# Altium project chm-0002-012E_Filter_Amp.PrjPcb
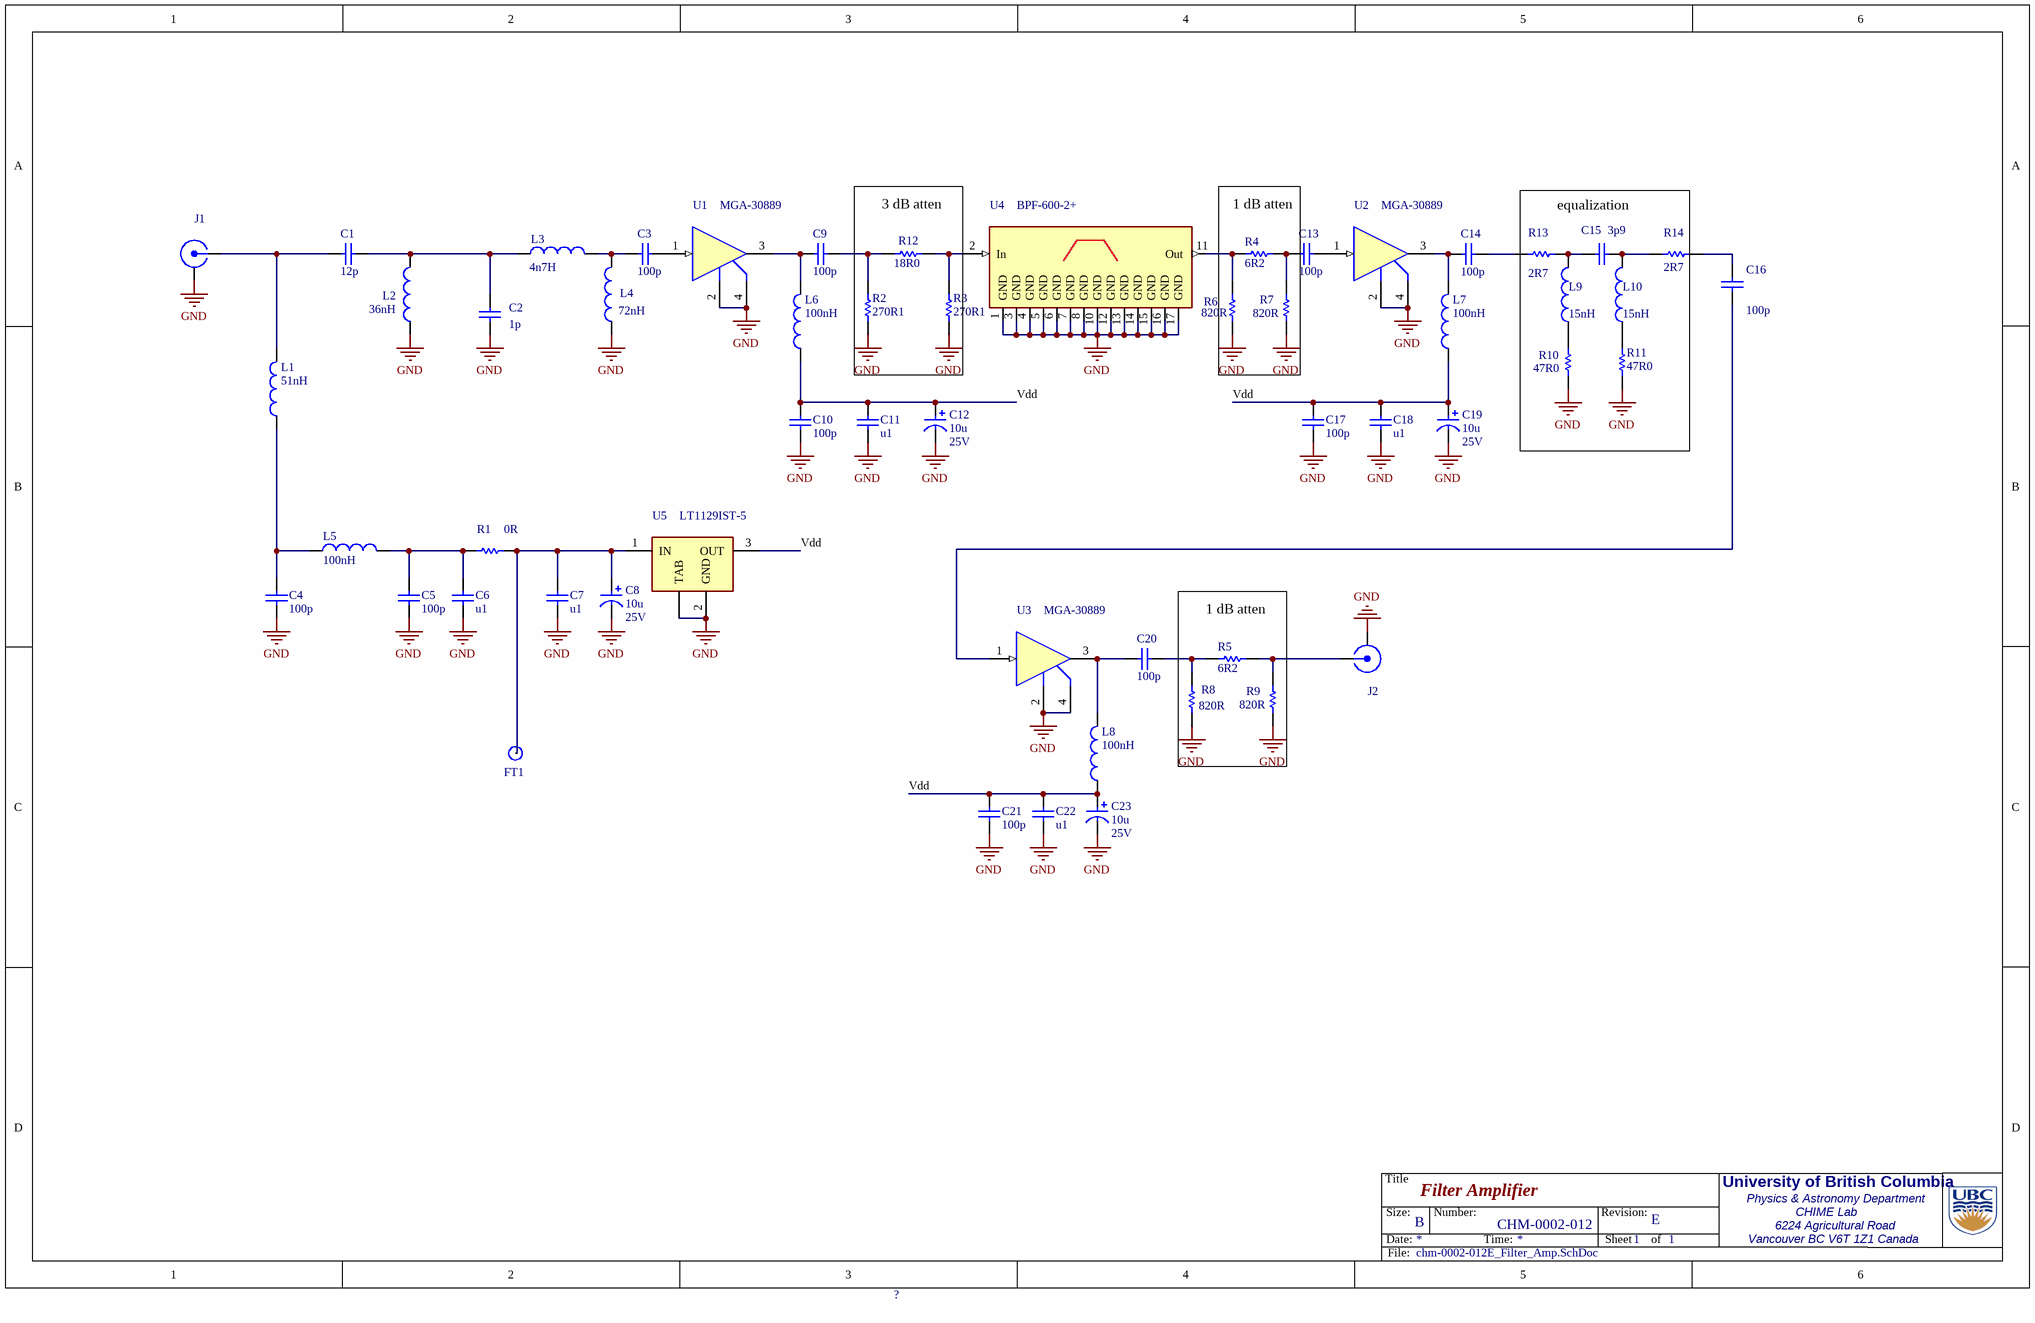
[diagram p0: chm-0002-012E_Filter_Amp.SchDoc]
ASYNumber: 00XXXX ASY; Board#: ****; BOMTitle: CHIME - Filter Amplifier; PO_Number: ****; Project: CHIME Project; Rev: CHM-0002-012 Rev E; Speedchart: LSCS
1 sheet, 56 parts. Net scope: global (net labels, ports and power ports of the same name join across sheets).
Board file: chm-0002-012E_Filter_Amp.PcbDoc

## Sheet chm-0002-012E_Filter_Amp.SchDoc: Filter Amplifier
size B; DrawnBy: V.Soutyrine; Engineer: Rick Smegal; Organization: University of British Columbia; Address1: Physics & Astronomy Department; Address2: CHIME Lab; Address3: 6224 Agricultural Road; Address4: Vancouver BC V6T 1Z1 Canada; DocumentNumber: CHM-0002-012; Revision: E; SheetNumber: 1; SheetTotal: 1

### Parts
?  UBC Logo  [UBC Logo]  (value not drawn)
C1  value 12p  [C1608-0603]  (hidden comment: C0603_12p)
C2  value 1p  [C1608-0603]  (hidden comment: C0603_1p)
C3  value 100p  [C1608-0603]  (hidden comment: C0603_100p)
C4  value 100p  [C1608-0603]  (hidden comment: C0603_100p)
C5  value 100p  [C1608-0603]  (hidden comment: C0603_100p)
C6  value u1  [C1608-0603]  (hidden comment: C0603_u1)
C7  value u1  [C1608-0603]  (hidden comment: C0603_u1)
C8  value 10u  Voltage: 25V  [CC3528]  (hidden comment: Cap Tant 10uF 25V Low ESR)
C9  value 100p  [C1608-0603]  (hidden comment: C0603_100p)
C10  value 100p  [C1608-0603]  (hidden comment: C0603_100p)
C11  value u1  [C1608-0603]  (hidden comment: C0603_u1)
C12  value 10u  Voltage: 25V  [CC3528]  (hidden comment: Cap Tant 10uF 25V Low ESR)
C13  value 100p  [C1608-0603]  (hidden comment: C0603_100p)
C14  value 100p  [C1608-0603]  (hidden comment: C0603_100p)
C15  value 3p9  [C1608-0603]  (hidden comment: C0603_3p9)
C16  value 100p  [C1608-0603]  (hidden comment: C0603_100p)
C17  value 100p  [C1608-0603]  (hidden comment: C0603_100p)
C18  value u1  [C1608-0603]  (hidden comment: C0603_u1)
C19  value 10u  Voltage: 25V  [CC3528]  (hidden comment: Cap Tant 10uF 25V Low ESR)
C20  value 100p  [C1608-0603]  (hidden comment: C0603_100p)
C21  value 100p  [C1608-0603]  (hidden comment: C0603_100p)
C22  value u1  [C1608-0603]  (hidden comment: C0603_u1)
C23  value 10u  Voltage: 25V  [CC3528]  (hidden comment: Cap Tant 10uF 25V Low ESR)
FT1  #6 Clearance Drill  [#6 Clearance Drill]  (value not drawn)
J1  SMA-Edgemount  [SMA_EdgeConnector]  (value not drawn)
J2  SMA-Edgemount  [SMA_EdgeConnector]  (value not drawn)
L1  value 51nH  [R0603]  (hidden comment: Ind0603_51nH)
L2  value 36nH  [R0603]  (hidden comment: Ind0603_36nH)
L3  value 4n7H  [R0603]  (hidden comment: Ind0603_4n7H)
L4  value 72nH  [R0603]  (hidden comment: Ind0603_72nH)
L5  value 100nH  [0805 LRC]  (hidden comment: Ind0805_100nH)
L6  value 100nH  [R0603]  (hidden comment: Ind0603_100nH)
L7  value 100nH  [R0603]  (hidden comment: Ind0603_100nH)
L8  value 100nH  [R0603]  (hidden comment: Ind0603_100nH)
L9  value 15nH  [R0603]  (hidden comment: Ind0603_15nH)
L10  value 15nH  [R0603]  (hidden comment: Ind0603_15nH)
R1  value 0R  [0805 LRC]  (hidden comment: R0805_0R)
R2  value 270R1  [R0603]  (hidden comment: R603_270R1)
R3  value 270R1  [R0603]  (hidden comment: R603_270R1)
R4  value 6R2  [R0603]  (hidden comment: R603_6R2)
R5  value 6R2  [R0603]  (hidden comment: R603_6R2)
R6  value 820R  [R0603]  (hidden comment: R603_82R1)
R7  value 820R  [R0603]  (hidden comment: R603_82R1)
R8  value 820R  [R0603]  (hidden comment: R603_82R1)
R9  value 820R  [R0603]  (hidden comment: R603_82R1)
R10  value 47R0  [R0603]  (hidden comment: R603_47R0)
R11  value 47R0  [R0603]  (hidden comment: R603_47R0)
R12  value 18R0  [R0603]  (hidden comment: R603_18R0)
R13  value 2R7  [R0603]  (hidden comment: R603_2R7)
R14  value 2R7  [R0603]  (hidden comment: R603_2R7)
U1  MGA-30889  [SOT-89]
U2  MGA-30889  [SOT-89]
U3  MGA-30889  [SOT-89]
U4  BPF-600-2+  [MiniCcts_HP1156]
U5  LT1129IST-5  [SOT-223]

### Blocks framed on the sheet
3 dB atten: R2 R3 R12
1 dB atten: R4 R6 R7
equalization: C15 L9 L10 R10 R11 R13 R14
1 dB atten: R5 R8 R9

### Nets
GND: C2.1 C4.1 C5.1 C6.1 C7.1 C8.2 C10.1 C11.1 C12.2 C17.1 C18.2 C19.2 C21.1 C22.1 C23.2 J1.2(Y) J2.2(Y) L2.1 L4.1 R2.1 R3.1 R6.1 R7.1 R8.1 R9.1 R10.1 R11.2 U1.2(GND) U1.4(GND) U2.2(GND) U2.4(GND) U3.2(GND) U3.4(GND) U4.1(GND) U4.3(GND) U4.4(GND) U4.5(GND) U4.6(GND) U4.7(GND) U4.8(GND) U4.10(GND) U4.12(GND) U4.13(GND) U4.14(GND) U4.15(GND) U4.16(GND) U4.17(GND) U5.2(GND) U5.4(TAB)
Vdd: C10.2 C11.2 C12.1 C17.2 C18.1 C19.1 C21.2 C22.2 C23.1 L6.1 L7.1 L8.1 U5.3(OUT)
NetC1_1: C1.1 J1.1(X) L1.2
NetC1_2: C1.2 C2.2 L2.2 L3.1
NetC3_1: C3.1 L3.2 L4.2
NetC3_2: C3.2 U1.1(IN)
NetC4_2: C4.2 L1.1 L5.1
NetC5_2: C5.2 C6.2 L5.2 R1.1
NetC7_2: C7.2 C8.1 FT1.1 R1.2 U5.1(IN)
NetC9_1: C9.1 L6.2 U1.3(OUT/DCIN)
NetC9_2: C9.2 R2.2 R12.1
NetC13_1: C13.1 R4.2 R7.2
NetC13_2: C13.2 U2.1(IN)
NetC14_1: C14.1 L7.2 U2.3(OUT/DCIN)
NetC14_2: C14.2 R13.1
NetC15_1: C15.1 L9.2 R13.2
NetC15_2: C15.2 L10.2 R14.1
NetC16_1: C16.1 U3.1(IN)
NetC16_2: C16.2 R14.2
NetC20_1: C20.1 L8.2 U3.3(OUT/DCIN)
NetC20_2: C20.2 R5.1 R8.2
NetJ2_1: J2.1(X) R5.2 R9.2
NetL9_1: L9.1 R10.2
NetL10_1: L10.1 R11.1
NetR3_2: R3.2 R12.2 U4.2(In)
NetR4_1: R4.1 R6.2 U4.11(Out)

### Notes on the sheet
- Title
- Size:
- Date:
- B
- Number:
- Time:
- Revision:
- Sheet
- of
- File:

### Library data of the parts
C1 = C0603_12p: 12pf 1% 0603 50V NPO; Manufacturer: MuRata; Part Number: GRM0885C1H120FA01; Class: Passive; Fitted: POP; MCE#: 002889 Cap; SubClass: Capacitor; Type: SMD
C2 = C0603_1p: 1pF +-0.1pF 100V 0603 cer capacitor; Manufacturer: AVX; Part Number: 06031A1R0BAT2A; Class: Passive; Fitted: POP; MCE#: 002907 CAP; Type: SMD
C3-C5 C9 C10 C13 C14 C16 C17 C20 C21 = C0603_100p: 100pf Ceramic NPO 0603 Capacitor; Manufacturer: Generic; Part Number: 06035A101KAT2A; Class: Passive; Fitted: POP; MCE#: 000268 CAP; Type: SMD
C6 C7 C11 C18 C22 = C0603_u1: u1 Ceramic X7R 0603 Capacitor; Manufacturer: TDK Corporation; Part Number: C1608X7R1H104K; Class: Passive; Fitted: POP; MCE#: 000271 CAP; Type: SMD
C8 C12 C19 C23 = Cap Tant 10uF 25V Low ESR: Manufacturer: Kemet; Part Number: T491B106K025AT; Class: Passive; Fitted: POP; MCE#: 002891 CAP; SubClass: Capacitor; Type: SMD
C15 = C0603_3p9: 3.9pf  +-.1pf 0603 50V NPO; Manufacturer: Samsung; Part Number: CL10C3R9BB8NNNC; Class: Passive; Fitted: POP; MCE#: 002890 CAP; SubClass: Capacitor; Type: SMD
FT1 = #6 Clearance Drill: Feed Through Filter; Manufacturer: API Technologies; Part Number: 51-703-007; Designator: FT1; MCE#: 002892 CAP
J1 J2 = SMA-Edgemount: SMA long edge launch connectors female; Manufacturer: Linx Technologies; Part Number: CONSMA003.062-L; Fitted: POP; MCE#: 002586 CON
L1 = Ind0603_51nH: 51nH 2% 0603 370mA; Manufacturer: MuRata; Part Number: LQW18AN51NG00; Class: Passive; Fitted: POP; MCE#: 002882 IND; SubClass: Inductor; Type: SMD
L2 = Ind0603_36nH: 36nH 2% 0603; Manufacturer: MuRata; Part Number: LQW18AN36NG00; Class: Passive; Fitted: POP; MCE#: 002884 IND; SubClass: Inductor; Type: SMD
L3 = Ind0603_4n7H: 4.7nH 2% RF Inductor; Manufacturer: Coilcraft; Part Number: 0603CS_4N7XGE(U); Class: Passive; Fitted: POP; MCE#: 002887 IND; Type: SMD
L4 = Ind0603_72nH: 72nH 2% 0603; Manufacturer: MuRata; Part Number: LQW18AN72NG00; Class: Passive; Fitted: POP; MCE#: 002883 IND; SubClass: Inductor; Type: SMD
L5 = Ind0805_100nH: 100nH 0805 Inductor; Manufacturer: Murata; Part Number: LQW2BASR10J00L; Class: Passive; Fitted: POP; Type: SMD; MCE#: 002071 IND
L6-L8 = Ind0603_100nH: 100nH 0603 5% 220mA; Manufacturer: Murata; Part Number: LQW18ANR10J00; Class: Passive; Fitted: POP; MCE#: 002886 IND; SubClass: Inductor; Type: SMD
L9 L10 = Ind0603_15nH: 15nH 2% 0603; Manufacturer: MuRata; Part Number: LQW18AN15NG00(D); Class: Passive; Fitted: POP; MCE#: 002885 IND; SubClass: Inductor; Type: SMD
R1 = R0805_0R: 0R 0805 1% Resistor; Manufacturer: Stackpole; Part Number: RMCF0805ZT0R00; MCE#: 000253 RES; Class: Passive; Fitted: POP
R2 R3 = R603_270R1: 271R 0603 0.5% Thin Film 1/16W 100ppm Resistor; Manufacturer: Susumu; Part Number: RR0816P-271-D; Class: Passive; Fitted: POP; MCE#: 002878 RES
R4 R5 = R603_6R2: 6R2 0603 1/16W 1% 200ppm Thin Film Resistor; Manufacturer: Susumu; Part Number: RL0816S-6R2-F; Class: Passive; Fitted: POP; MCE#: 002876 RES
R6-R9 = R603_82R1: 820R 0.5% 25ppm 0603 Thin Film Resistor; Manufacturer: Susumu; Part Number: RR0816P-821-D; Class: Passive; Fitted: POP; MCE#: 002881 RES
R10 R11 = R603_47R0: 47R 1% 200ppm 1/5W 0603 Thin Film Resistor; Manufacturer: Susumu; Part Number: RL0816S-470-F; Class: Passive; Fitted: POP; MCE#: 002879 RES
R12 = R603_18R0: 18R 0603 1/16W 0.5% Thin Film Resistor; Manufacturer: Susumu; Part Number: RR0816Q-180-D; Class: Passive; Fitted: POP; MCE#: 002877 RES
R13 R14 = R603_2R7: 2R7 0603 1% 200ppm Thin Film Resistor; Manufacturer: Susumu; Part Number: RL0816S-2R7-F; Class: Passive; Fitted: POP; MCE#: 002880 RES
U1-U3 = MGA-30889: 40MHz-2600MHz Flat Gain High Linearity Gain Block MGA-30889; Manufacturer: Avago Tech; Revised: 2012-8-17TF; Class: Amplifier; SubClass: RF Amplifier; MCE#: 002514; POP/DNP: POP
U4 = BPF-600-2+: Band Pass Filter; Manufacturer: Mini-Ccts; MCE#: 002508 ICA
U5 = LT1129IST-5: LDO +5V Regulator 700mA; Manufacturer: Linear Technology; MCE#: 000167 ICA; Fitted: POP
